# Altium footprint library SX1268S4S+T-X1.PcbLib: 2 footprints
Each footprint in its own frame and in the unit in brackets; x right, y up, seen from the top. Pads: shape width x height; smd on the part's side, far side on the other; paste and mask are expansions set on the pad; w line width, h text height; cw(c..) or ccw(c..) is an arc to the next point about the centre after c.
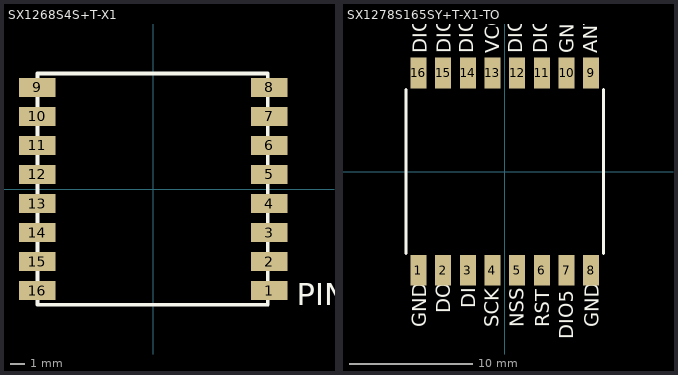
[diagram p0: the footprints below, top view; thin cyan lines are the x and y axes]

## SX1268S4S+T-X1 [mm]
pads (16):
  rect 2.5x1.3 smd: 1(8,-7) 2(8,-5) 3(8,-3) 4(8,-1) 5(8,1) 6(8,3) 7(8,5) 8(8,7) 9(-8,7) 10(-8,5) 11(-8,3) 12(-8,1) 13(-8,-1) 14(-8,-3) 15(-8,-5) 16(-8,-7)
Top Overlay:
  lines w0.25: -7.977,-7.988 -7.977,7.962 ; 7.893,-7.982 7.898,-7.977 7.898,7.962
  lines w0.254: -7.977,-7.988 7.887,-7.988 7.893,-7.982 ; -7.977,7.962 7.898,7.962
  text "PIN1" at 9.906,-8.001 h1.52

## SX1278S165SY+T-X1-TO [mm]
pads (16):
  rect 1.3x2.5 smd: 1(-7,-8) 2(-5,-8) 3(-3,-8) 4(-1,-8) 5(1,-8) 6(3,-8) 7(5,-8) 8(7,-8) 9(7,8) 10(5,8) 11(3,8) 12(1,8) 13(-1,8) 14(-3,8) 15(-5,8) 16(-7,8)
Top Overlay:
  lines w0.254: -8,-6.637 -8,6.637 ; 8,-6.637 8,6.637
  text "GND" at 7.621,-12.619 h1.14
  text "DIO5" at 5.562,-13.571 h1.14
  text "RST" at 3.581,-12.619 h1.14
  text "NSS" at 1.523,-12.619 h1.14
  text "SCK" at -0.509,-12.619 h1.14
  text "DI" at -2.387,-11.095 h1.14
  text "DO" at -4.42,-11.476 h1.14
  text "GND" at -6.375,-12.619 h1.14
  text "DIO2" at -6.333,9.602 h1.14
  text "DIO1" at -4.403,9.602 h1.14
  text "DIO0" at -2.551,9.602 h1.14
  text "VCC" at -0.451,9.602 h1.14
  text "DIO4" at 1.411,9.602 h1.14
  text "DIO3" at 3.438,9.602 h1.14
  text "GND" at 5.579,9.602 h1.14
  text "ANT" at 7.483,9.602 h1.14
